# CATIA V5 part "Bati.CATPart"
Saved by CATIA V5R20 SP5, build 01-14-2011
Part number: Bati
Bounding box of the stored display mesh (mm): x -70 to 70, y -45 to 315, z -20 to 0
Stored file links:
  F:\IAO_bmadec\bmadecf\Bati.CATPart
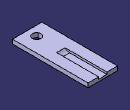
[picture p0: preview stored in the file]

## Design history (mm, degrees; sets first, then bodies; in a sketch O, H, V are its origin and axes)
Body1 (main body)
  Sketch1 on xy-plane, origin (0, 0, 0), H (1, 0, 0), V (0, 1, 0)
    line L1 (70, -45) -> (-70, -45)
    line L2 (-70, -45) -> (-70, 315)
    line L3 (-70, 315) -> (70, 315)
    line L4 (70, 315) -> (70, -45)
    distance L4 V = 70
    distance L1 H = 45
    length L4 = 360
    horizontal: L1 H, L3 H
    vertical: L2 V, L4 V
    symmetry: L4 L2 V
  Pad1: profile Sketch1, direction (0, 0, -1), length 20
  Sketch2 on end face of Pad1, origin (-11.4223, 5.4348, -20), H (1, 0, 0), V (0, -1, 0)
    point P1 (11.4223, 5.4348)
    reference intersected line E1 through (0, 5.4348) direction (1, 0) from zx-plane
    reference intersected line E2 through (11.4223, 0) direction (0, 1) from yz-plane
    coincidence: P1 E1, P1 E2
  Hole1: placed by Sketch2, at (0, 0, -20) direction (0, 0, 1), diameter 40, through (limit type 6)
  Sketch3 on yz-plane, origin (0, 0, 0), H (0, 1, 0), V (0, 0, 1)
    point P1 (315, 0)
    line L1 (315, 0) -> (315, -10)
    line L2 (315, -10) -> (137.3607, -10)
    arc A1 centre (137.3607, 20) radius 30 from (137.3607, -10) to (115, 0) cw
    point P5 (115, 0)
    point P6 (137.3607, -10)
    reference projected line E1 (-45, 0) -> (315, 0) from edge [face of Pad1 from Sketch1.L4 | start face of Pad1]
    line L3 (115, 0) -> (315, 0)
    reference projected line E2 (315, 0) -> (315, -20) from edge [face of Pad1 from Sketch1.L4 | face of Pad1 from Sketch1.L3]
    distance L2 E1 = 10
    radius A1 = 30
    length L3 = 200
    coincidence: P1 H, P5 H, A1 P6, P6 L2, L1 E2
    vertical: L1 V
    horizontal: L2 H, L3 H
    tangency: A1 L2
  Pocket1: profile Sketch3, direction (-1, 0, 0), length 20, opposite side length 20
